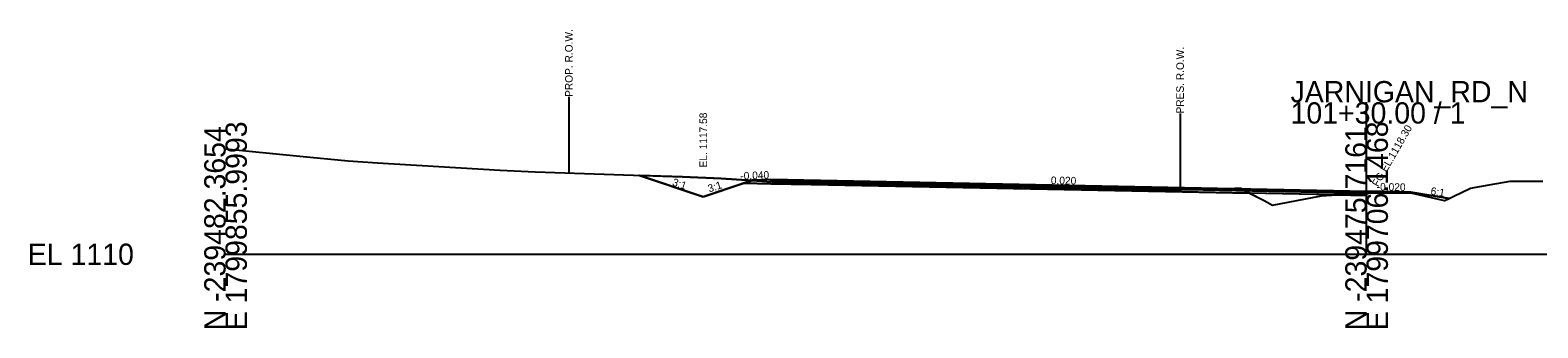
# Model space of a CAD drawing. Extents: x 214513 to 217151, y 214739 to 216780.
# Drawn here: x 215422.7 to 215620.9, y 216238.7 to 216277.9 of the extents above; entities that cross this region are included whole.
import ezdxf

# ---------------------------------------------------------------- set-up
doc = ezdxf.new("R2010")
doc.units = 0
for name, color, linetype in [('CONCEPT - TRANSPORTATION - Roads Text', 7, 'Continuous'), ('DESIGN - CENTERLINE - Proposed', 7, 'Continuous'), ('DESIGN - CENTERLINE - Proposed Text', 7, 'Continuous'), ('DESIGN - DRAINAGE - Special Ditches', 7, 'Continuous'), ('DESIGN - EARTHWORK - Shapes', 7, 'Continuous'), ('DESIGN - ROW - Right-of-Way Linework', 7, 'Continuous'), ('DESIGN - TRANSPORTATION - Text', 7, 'Continuous'), ('DESIGN - TYPICAL - Slope Tie Text', 7, 'Continuous'), ('Section', 7, 'Continuous'), ('SURVEY - DTM GRAPHICS - Triangles', 7, 'Continuous'), ('SURVEY - PROPERTY - ROW Lines', 7, 'Continuous'), ('XSCell', 7, 'Continuous')]:
    doc.layers.add(name, color=color, linetype=linetype)

msp = doc.modelspace()

# ---------------------------------------------------------------- linework, layer by layer
at = {"layer": 'DESIGN - DRAINAGE - Special Ditches'}
for points in [[(215511.16, 216255.94), (215502.76, 216258.74)], [(215517.76, 216258.14), (215511.16, 216255.94)], [(215520.05, 216258.23), (215520.05, 216257.98), (215525.34, 216257.88), (215598.36, 216256.41), (215598.36, 216256.08), (215525.34, 216257.55), (215520.05, 216257.65), (215516.51, 216257.72), (215517.76, 216258.14), (215520.05, 216258.23)], [(215520.05, 216258.23), (215598.36, 216256.66), (215598.36, 216256.56), (215598.36, 216256.56), (215520.05, 216258.13), (215520.05, 216258.13), (215520.05, 216258.13), (215520.05, 216258.23), (215520.05, 216258.23)], [(215520.05, 216258.13), (215598.36, 216256.56), (215598.36, 216256.41), (215598.36, 216256.41), (215520.05, 216257.98), (215520.05, 216257.98), (215520.05, 216257.98), (215520.05, 216258.13), (215520.05, 216258.13)], [(215604.17, 216256.55), (215598.36, 216256.66), (215598.36, 216256.56), (215598.36, 216256.56), (215604.17, 216256.45), (215604.17, 216256.45), (215604.17, 216256.45), (215604.17, 216256.55), (215604.17, 216256.55)], [(215604.17, 216256.55), (215609.23, 216255.7)]]:
    msp.add_lwpolyline(points, dxfattribs=at)
at = {"layer": 'DESIGN - EARTHWORK - Shapes'}
for p, q in [((215502.76, 216258.74), (215511.16, 216255.94)), ((215517.54, 216258.07), (215516.51, 216257.72)), ((215582.34, 216256.74), (215574.72, 216256.89)), ((215574.72, 216256.89), (215582.34, 216256.74)), ((215581.05, 216257.01), (215578.91, 216256.95)), ((215582.03, 216256.89), (215578.91, 216256.95)), ((215578.91, 216256.95), (215582.03, 216256.89)), ((215581.05, 216257.01), (215581.83, 216257)), ((215581.83, 216257), (215581.05, 216257.01)), ((215582.03, 216256.89), (215581.83, 216257)), ((215582.34, 216256.74), (215582.03, 216256.89)), ((215583.01, 216256.39), (215582.34, 216256.74)), ((215594.23, 216256.17), (215583.01, 216256.39)), ((215594.23, 216256.17), (215598.36, 216256.08)), ((215598.36, 216256.56), (215598.36, 216256.41)), ((215598.36, 216256.41), (215598.36, 216256.4)), ((215598.36, 216256.08), (215598.36, 216256.4)), ((215609.23, 216255.7), (215604.17, 216256.55))]:
    msp.add_line(p, q, dxfattribs=at)
for points in [[(215517.54, 216258.07), (215513.53, 216258.33), (215508.45, 216258.54), (215502.76, 216258.74)], [(215511.16, 216255.94), (215516.51, 216257.72), (215517.54, 216258.07)], [(215516.51, 216257.72), (215520.05, 216257.65), (215525.34, 216257.55), (215583.01, 216256.39)], [(215574.72, 216256.89), (215566.2, 216256.87), (215553.13, 216257.07), (215531.74, 216257.58), (215521.52, 216257.8), (215517.54, 216258.07)], [(215578.91, 216256.95), (215576.61, 216256.89), (215574.72, 216256.89)], [(215581.83, 216257), (215581.76, 216257.03), (215581.05, 216257.01)], [(215583.01, 216256.39), (215584.9, 216255.43), (215586.01, 216254.81), (215591.23, 216255.85), (215592.41, 216256.06), (215594.23, 216256.17)], [(215598.36, 216256.4), (215597.15, 216256.34), (215594.23, 216256.17)], [(215604.17, 216256.55), (215604.17, 216256.45), (215598.36, 216256.56)], [(215598.36, 216256.4), (215598.64, 216256.42), (215599.16, 216256.43), (215604.17, 216256.44), (215608.57, 216255.42), (215608.62, 216255.41), (215608.65, 216255.43), (215609.23, 216255.7)]]:
    msp.add_lwpolyline(points, dxfattribs=at)
at = {"layer": 'DESIGN - ROW - Right-of-Way Linework'}
msp.add_lwpolyline([(215493.49, 216269.07), (215493.49, 216259.07)], dxfattribs=at)
at = {"layer": 'SURVEY - DTM GRAPHICS - Triangles'}
msp.add_lwpolyline([(215448.36, 216262.22), (215458.12, 216261.25), (215464.46, 216260.65), (215468.34, 216260.39), (215484.46, 216259.44), (215489.07, 216259.22), (215490.38, 216259.18), (215508.45, 216258.54), (215513.53, 216258.33), (215521.52, 216257.8), (215531.74, 216257.58), (215553.13, 216257.07), (215566.2, 216256.87), (215576.61, 216256.89), (215581.76, 216257.03), (215584.9, 216255.43), (215586.01, 216254.81), (215591.23, 216255.85), (215592.41, 216256.06), (215597.15, 216256.34), (215598.64, 216256.42), (215599.16, 216256.43), (215604.17, 216256.44), (215608.57, 216255.42), (215608.62, 216255.41), (215608.65, 216255.43), (215612.03, 216257.04), (215614.48, 216257.51), (215617.22, 216257.98), (215621.53, 216257.97)], dxfattribs=at)
at = {"layer": 'SURVEY - PROPERTY - ROW Lines'}
msp.add_lwpolyline([(215573.84, 216266.89), (215573.84, 216256.89)], dxfattribs=at)
at = {"layer": 'XSCell'}
for p, q in [((215598.36, 216248.36), (215598.36, 216268.36)), ((215448.36, 216248.36), (215598.36, 216248.36)), ((215598.36, 216248.36), (215748.36, 216248.36))]:
    msp.add_line(p, q, dxfattribs=at)

# ---------------------------------------------------------------- texts
at = {"layer": 'CONCEPT - TRANSPORTATION - Roads Text'}
for s, rotation, p in [('-0.040', 2.2906, (215516.05, 216258.17)), ('0.020', 358.8542, (215556.84, 216257.6)), ('-0.020', 358.8542, (215599.68, 216256.76))]:
    msp.add_text(s, height=1, rotation=rotation, dxfattribs=at).set_placement(p)
at = {"layer": 'DESIGN - CENTERLINE - Proposed'}
msp.add_text('EL. 1117.58', height=1, rotation=90, dxfattribs=at).set_placement((215511.66, 216259.79))
at = {"layer": 'DESIGN - CENTERLINE - Proposed Text'}
msp.add_text('FG EL.1118.30', height=1, rotation=60, dxfattribs=at).set_placement((215599.86, 216257.16))
at = {"layer": 'DESIGN - TRANSPORTATION - Text'}
for s, p in [('PROP. R.O.W.', (215493.99, 216269.07)), ('PRES. R.O.W.', (215574.34, 216266.89))]:
    msp.add_text(s, height=1, rotation=90, dxfattribs=at).set_placement(p)
at = {"layer": 'DESIGN - TYPICAL - Slope Tie Text'}
for s, rotation, p in [('3:1', 341.5651, (215507, 216257.44)), ('3:1', 18.4349, (215511.95, 216256.49)), ('6:1', 350.5377, (215606.72, 216256.23))]:
    msp.add_text(s, height=1, rotation=rotation, dxfattribs=at).set_placement(p)
at = {"layer": 'Section'}
msp.add_text('-', height=0.0001, dxfattribs=at).set_placement((215448.36, 216248.36))
at = {"layer": 'XSCell'}
for s, p in [('JARNIGAN_RD_N', (215588.36, 216268.36)), ('101+30.00 / 1', (215588.36, 216265.56)), ('EL 1110', (215422.36, 216246.96))]:
    msp.add_text(s, height=2.8, dxfattribs=at).set_placement(p)
for s, p in [('E 1799855.9993', (215451.16, 216238.36)), ('E 1799706.1468', (215601.16, 216238.36)), ('N -239482.3654', (215448.36, 216238.36)), ('N -239475.7161', (215598.36, 216238.36))]:
    msp.add_text(s, height=2.8, rotation=90, dxfattribs=at).set_placement(p)

doc.saveas('drawing.dxf')
